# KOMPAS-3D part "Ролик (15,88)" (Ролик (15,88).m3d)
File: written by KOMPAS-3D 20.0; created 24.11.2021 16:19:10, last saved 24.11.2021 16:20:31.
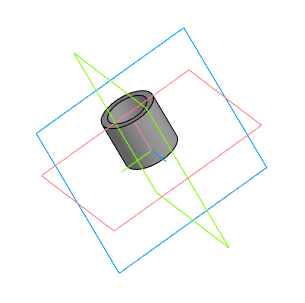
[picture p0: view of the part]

Document properties: Полное имя файла: C:\!WORK!\ЗИГ-18.240.00\Цепь\Ролик (15,88).m3d

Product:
- Part/product: Ролик (15,88)
    Материал: Сталь 45  ГОСТ 1050-2013 (density 7810 kg/m3)
    Масса: 0.00968765

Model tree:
1. Эскиз:1
2. Элемент выдавливания:1  (labels: Сталь 45  ГОСТ 1050-2013)
     Расстояние 1 = 14.6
